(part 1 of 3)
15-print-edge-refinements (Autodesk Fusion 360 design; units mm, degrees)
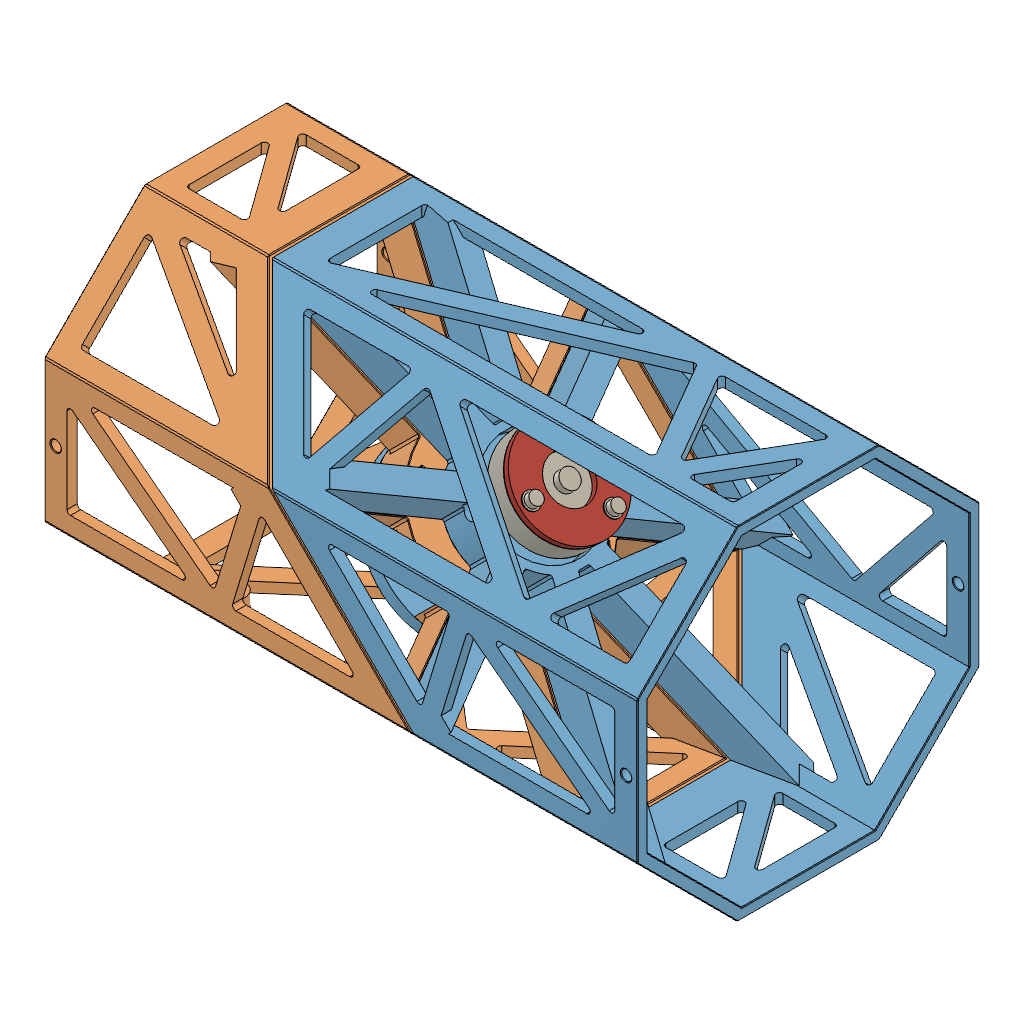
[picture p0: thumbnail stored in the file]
part number: 2026-11-02-20-17-55-344
part number: 2026-11-02-20-17-59-218
part number: 2026-11-02-20-17-59-224
part number: 2026-11-02-20-19-00-695
part number: 2026-11-02-20-19-03-009
part number: 2026-11-02-20-19-04-949
part number: 2026-11-02-20-19-06-912
part number: 2026-11-02-20-19-11-903
part number: 2026-11-02-20-19-12-666
part number: 2026-11-02-20-19-12-978
part number: 2026-11-02-20-19-13-740
part number: 2026-11-02-20-19-14-532
part number: 2026-11-02-20-19-15-361
part number: 2026-11-02-20-19-17-468
part number: 2026-11-02-20-19-19-583
part number: 2026-11-02-20-19-25-638
part number: 2026-11-02-20-19-39-091
parameter "bodyWidth" = 150 comment "Regular octagon across flats; corner diameter is larger."
parameter "bodyLength" = 260 comment "Overall straight length of the shared master blank."
parameter "splitAngle" = 45 comment "Keep this lesson angle at45 degrees."
parameter "faceGap" = 1 comment "Gap between the two printed joint faces."
parameter "wall" = 4.5 comment "Integrated shell and side brace radial thickness."
parameter "faceHalfWidth" = 31.066 (= "bodyWidth * ( sqrt(2) - 1 ) / 2") comment "Half-width of each outer planar facet."
parameter "memberWidth" = 8 comment "Nominal brace and corner chord width in a facet."
parameter "nodeHalfWidth" = 27.066 (= "faceHalfWidth - memberWidth / 2") comment "Chord centerlines measured from facet center."
parameter "jointNodeQ" = 7 comment "First truss skeleton row from the center joint plane."
parameter "endRim" = 10 comment "Uncut axial rim at each distant end."
parameter "endNodeX" = 124 (= "bodyLength / 2 - endRim + memberWidth / 2") comment "Last skeleton row before aperture inset."
parameter "apertureRadius" = 1.5 comment "Rounded internal corners at triangular openings."
parameter "spokeWidth" = 10 comment "Width of each deep bearing bulkhead spoke."
parameter "spokeDepth" = 18 comment "Bulkhead depth normal to the diagonal joint face."
parameter "carrierOD" = 52 comment "Outside of integrated A front bearing carrier."
parameter "rearCarrierClearance" = 46 comment "Internal carrier relief above front bearing shoulder."
parameter "tubeCornerChamfer" = 0.5 comment "Exposed outside octagon corner bevel."
parameter "tubeRimChamfer" = 0.3 comment "End rim and print-contact edge relief."
parameter "cordStation" = 125 (= "bodyLength / 2 - endRim / 2") comment "Load-test cord port center measured along body X."
parameter "bearingOD" = 22 comment "608 measured outside diameter."
parameter "bearingID" = 8 comment "608 bore."
parameter "bearingWidth" = 7 comment "608 width."
parameter "seatAllowance" = 0.2 comment "Trial DIAMETRAL clearance; choose with printed coupon."
parameter "seatDiameter" = 22.2 (= "bearingOD + seatAllowance") comment "Measured fit controls this."
parameter "coreOD" = 44 comment "Bearing holder outer diameter."
parameter "raceRelief" = 19.5 comment "Outer-ring shoulder opening; verify seals."
parameter "frontSeatDepth" = 7.1 comment "0.1 mm outer-ring axial allowance."
parameter "rearSeatDepth" = 7.2 comment "0.2 mm outer-ring axial float."
parameter "shoulder" = 3 comment "Backing behind each bearing seat."
parameter "supportSpacer" = 12 comment "Purchased metal M3 spacer length."
parameter "supportCircle" = 34 comment "Three M3 support bolts."
parameter "supportSpacerOD" = 6 comment "Purchased spacer outside diameter."
parameter "capThickness" = 3 comment "Both printed outer-ring retaining caps."
parameter "m3Clearance" = 3.3 comment "M3 through holes."
parameter "m4Clearance" = 4.3 comment "M4 through holes."
parameter "qFront" = 0.5 (= "faceGap / 2") comment "Front bearing starts at A mating face."
parameter "qFrontBack" = 10.6 (= "qFront + frontSeatDepth + shoulder") comment "End of integrated A holder."
parameter "qRearBase" = 22.6 (= "qFrontBack + supportSpacer") comment "Start of removable rear holder."
parameter "qRearBearing" = 25.6 (= "qRearBase + shoulder") comment "Rear bearing inner end."
parameter "qRearEnd" = 32.8 (= "qRearBearing + rearSeatDepth") comment "Rear holder outer end."
parameter "bearingSpacing" = 25.1 (= "qRearBearing - qFront") comment "Derived support-center spacing, not a bearing rating."
parameter "mountOD" = 76 comment "B mount and F flange outside diameter."
parameter "mountCircle" = 64 comment "Four M4 attachment holes."
parameter "mountOpening" = 50.3 comment "B through opening."
parameter "hubFace" = -23 comment "Metal hub flat mounting face."
parameter "adapterThickness" = 6 comment "F flange and metal compression sleeve length."
parameter "pilotDiameter" = 50 comment "F shallow centering pilot."
parameter "pilotInside" = 34 comment "Clearance around metal hub."
parameter "pilotHeight" = 2 comment "Short pilot only."
parameter "hubHoleSpacing" = 16 comment "Metal Sonic hub square hole spacing."
parameter "sleeveOD" = 8 comment "M4 metal compression sleeves."
parameter "sleeveAllowance" = 0.2 comment "Trial DIAMETRAL sleeve clearance."
parameter "shaftClearance" = 8.5 comment "F clearance hole; not a bearing."
parameter "nutAF" = 7.2 comment "M4 nominal 7 AF nut trial pocket."
parameter "nutDepth" = 4 comment "Open front M4 nut pocket."
parameter "rootRadius" = 1 comment "Hub-to-wall blend."
parameter "entryChamfer" = 0.4 comment "Assembly lead-in."
parameter "bedRelief" = 0.3 comment "Bed-contact edge allowance."
parameter "driverPort" = 5 comment "Clearance for bare3 mm hex-key shafts; bulky bit holders do not fit."
parameter "accessPadWidth" = 12 comment "Reinforced access-port capsule width."
parameter "accessPadExtra" = 2 comment "Local inward reinforcement beyond nominal side wall."
parameter "printEntryRelief" = 0.3 comment "Small nut, sleeve and free shaft-hole bed-mouth lead-in; not a bore size."
sketch "01 Master Octagon" plane through (0, 0, 0) normal (1, 0, 0) x axis (0, 0, -1)
  line L1 (31.066, 75) -> (75, 31.066)
  line L2 (-31.066, 75) -> (31.066, 75)
  line L3 (-75, 31.066) -> (-31.066, 75)
  line L4 (-75, -31.066) -> (-75, 31.066)
  line L5 (-31.066, -75) -> (-75, -31.066)
  line L6 (31.066, -75) -> (-31.066, -75)
  line L7 (75, -31.066) -> (31.066, -75)
  line L8 (75, 31.066) -> (75, -31.066)
  point P1 (0, 0)
  point P10 (0, 0)
  point P3 (31.066, 75)
  point P8 (31.066, -75)
  coincident P1 P10
  horizontal L2
  dimension "d59" distance P3 P8 = 150 (= "bodyWidth")
extrude "Extrude1" new body sketch "01 Master Octagon" distance 260 (= "bodyLength")
work_plane "WorkPlane1" RotateAngle 45 (= "splitAngle") ExtraOffset 0
split "Split1"
offset_faces "OffsetFaces1" distance -0.5 (= "-faceGap / 2")
offset_faces "OffsetFaces2" distance -0.5 (= "-faceGap / 2")
component_from_bodies "Body->Comp1"
component_from_bodies "Body->Comp2"
shell "Shell1" innerThickness 4.5 (= "wall")
shell "Shell1" innerThickness 4.5 (= "wall")
work_plane "WorkPlane1" RotateAngle -90 ExtraOffset 0
work_plane "WorkPlane2" AlongDistance 75 (= "bodyWidth / 2") ExtraOffset 0
sketch "A Facet 0 Triangle 1" plane through (0, 75, 0) normal (0, 1, 0) x axis (1, 0, 0)
  line L1 (-65.1005, -27.066) -> (-65.1005, 27.066)
  line L2 (60.9665, 27.066) -> (-65.1005, -27.066)
  line L3 (-65.1005, 27.066) -> (60.9665, 27.066)
  line L4 (-61.1005, -20.9953) -> (-61.1005, 23.066)
  line L5 (41.513, 23.066) -> (-61.1005, -20.9953)
  line L6 (-61.1005, 23.066) -> (41.513, 23.066)
  point P1 (0, 0)
  point P2 (-65.1005, 27.066)
  point P3 (-65.1005, -27.066)
  point P4 (60.9665, 27.066)
  dimension "d72" distance P1 P2 = 65.1005 (= "Linear Dimension-2")
  dimension "d73" distance P1 P2 = 27.066 (= "Linear Dimension-3")
  dimension "d74" distance P1 P3 = 65.1005 (= "Linear Dimension-4")
  dimension "d75" distance P1 P3 = 27.066 (= "Linear Dimension-5")
  dimension "d76" distance P1 P4 = 60.9665 (= "Linear Dimension-6")
  dimension "d77" distance P1 P4 = 27.066 (= "Linear Dimension-7")
  dimension "d78" = -4 (= "-memberWidth / 2")
extrude "Extrude1" cut sketch "A Facet 0 Triangle 1" profile of L5 L6 L4 against normal blind 4.7 (magnitude of "-( wall + 0.2 mm )")
sketch "A Facet 0 Triangle 2" plane through (0, 75, 0) normal (0, 1, 0) x axis (1, 0, 0)
  line L1 (60.9665, 27.066) -> (-65.1005, -27.066)
  line L2 (92.4832, -27.066) -> (60.9665, 27.066)
  line L3 (-65.1005, -27.066) -> (92.4832, -27.066)
  line L4 (59.2912, 21.9935) -> (-45.647, -23.066)
  line L5 (85.5258, -23.066) -> (59.2912, 21.9935)
  line L6 (-45.647, -23.066) -> (85.5258, -23.066)
  point P1 (0, 0)
  point P2 (-65.1005, -27.066)
  point P3 (60.9665, 27.066)
  point P4 (92.4832, -27.066)
  dimension "d81" distance P1 P2 = 65.1005 (= "Linear Dimension-2")
  dimension "d82" distance P1 P2 = 27.066 (= "Linear Dimension-3")
  dimension "d83" distance P1 P3 = 60.9665 (= "Linear Dimension-4")
  dimension "d84" distance P1 P3 = 27.066 (= "Linear Dimension-5")
  dimension "d85" distance P1 P4 = 92.4832 (= "Linear Dimension-6")
  dimension "d86" distance P1 P4 = 27.066 (= "Linear Dimension-7")
  dimension "d87" = 4 (= "memberWidth / 2")
extrude "Extrude2" cut sketch "A Facet 0 Triangle 2" profile of L5 L6 L4 against normal blind 4.7 (magnitude of "-( wall + 0.2 mm )")
sketch "A Facet 0 Triangle 3" plane through (0, 75, 0) normal (0, 1, 0) x axis (1, 0, 0)
  line L1 (92.4832, -27.066) -> (60.9665, 27.066)
  line L2 (124, 27.066) -> (92.4832, -27.066)
  line L3 (60.9665, 27.066) -> (124, 27.066)
  line L4 (92.4832, -19.1161) -> (67.924, 23.066)
  line L5 (117.0425, 23.066) -> (92.4832, -19.1161)
  line L6 (67.924, 23.066) -> (117.0425, 23.066)
  point P1 (0, 0)
  point P2 (60.9665, 27.066)
  point P3 (92.4832, -27.066)
  point P4 (124, 27.066)
  dimension "d90" distance P1 P2 = 60.9665 (= "Linear Dimension-2")
  dimension "d91" distance P1 P2 = 27.066 (= "Linear Dimension-3")
  dimension "d92" distance P1 P3 = 92.4832 (= "Linear Dimension-4")
  dimension "d93" distance P1 P3 = 27.066 (= "Linear Dimension-5")
  dimension "d94" distance P1 P4 = 124 (= "Linear Dimension-6")
  dimension "d95" distance P1 P4 = 27.066 (= "Linear Dimension-7")
  dimension "d96" = -4 (= "-memberWidth / 2")
extrude "Extrude3" cut sketch "A Facet 0 Triangle 3" profile of L5 L6 L4 against normal blind 4.7 (magnitude of "-( wall + 0.2 mm )")
sketch "A Facet 0 Triangle 4" plane through (0, 75, 0) normal (0, 1, 0) x axis (1, 0, 0)
  line L1 (124, 27.066) -> (92.4832, -27.066)
  line L2 (124, -27.066) -> (124, 27.066)
  line L3 (92.4832, -27.066) -> (124, -27.066)
  line L4 (120, 12.2459) -> (99.4407, -23.066)
  line L5 (120, -23.066) -> (120, 12.2459)
  line L6 (99.4407, -23.066) -> (120, -23.066)
  point P1 (0, 0)
  point P2 (92.4832, -27.066)
  point P3 (124, 27.066)
  point P4 (124, -27.066)
  dimension "d99" distance P1 P2 = 92.4832 (= "Linear Dimension-2")
  dimension "d100" distance P1 P2 = 27.066 (= "Linear Dimension-3")
  dimension "d101" distance P1 P3 = 124 (= "Linear Dimension-4")
  dimension "d102" distance P1 P3 = 27.066 (= "Linear Dimension-5")
  dimension "d103" distance P1 P4 = 124 (= "Linear Dimension-6")
  dimension "d104" distance P1 P4 = 27.066 (= "Linear Dimension-7")
  dimension "d105" = 4 (= "memberWidth / 2")
extrude "Extrude4" cut sketch "A Facet 0 Triangle 4" profile of L5 L6 L4 against normal blind 4.7 (magnitude of "-( wall + 0.2 mm )")
fillet "Fillet1" radius 1.5 (= "apertureRadius")
work_plane "WorkPlane3" RotateAngle -45 ExtraOffset 0
work_plane "WorkPlane4" AlongDistance 75 (= "bodyWidth / 2") ExtraOffset 0
sketch "A Facet 45 Triangle 1" plane through (0, 53.033, 53.033) normal (0, 0.7071, 0.7071) x axis (1, 0, 0)
  line L1 (-23.9949, -27.066) -> (-62.2721, 27.066)
  line L2 (-0.1814, 27.066) -> (-23.9949, -27.066)
  line L3 (-62.2721, 27.066) -> (-0.1814, 27.066)
  line L4 (-24.81, -18.9852) -> (-54.5447, 23.066)
  line L5 (-6.311, 23.066) -> (-24.81, -18.9852)
  line L6 (-54.5447, 23.066) -> (-6.311, 23.066)
  point P1 (0, 0)
  point P2 (-62.2721, 27.066)
  point P3 (-23.9949, -27.066)
  point P4 (-0.1814, 27.066)
  dimension "d114" distance P1 P2 = 62.2721 (= "Linear Dimension-2")
  dimension "d115" distance P1 P2 = 27.066 (= "Linear Dimension-3")
  dimension "d116" distance P1 P3 = 23.9949 (= "Linear Dimension-4")
  dimension "d117" distance P1 P3 = 27.066 (= "Linear Dimension-5")
  dimension "d118" distance P1 P4 = 0.1814 (= "Linear Dimension-6")
  dimension "d119" distance P1 P4 = 27.066 (= "Linear Dimension-7")
  dimension "d120" = -4 (= "-memberWidth / 2")
extrude "Extrude5" cut sketch "A Facet 45 Triangle 1" profile of L5 L6 L4 against normal blind 4.7 (magnitude of "-( wall + 0.2 mm )")
sketch "A Facet 45 Triangle 2" plane through (0, 53.033, 53.033) normal (0, 0.7071, 0.7071) x axis (1, 0, 0)
  line L1 (-0.1814, 27.066) -> (-23.9949, -27.066)
  line L2 (74.6684, -27.066) -> (-0.1814, 27.066)
  line L3 (-23.9949, -27.066) -> (74.6684, -27.066)
  line L4 (1.4863, 20.9235) -> (-17.8653, -23.066)
  line L5 (62.3117, -23.066) -> (1.4863, 20.9235)
  line L6 (-17.8653, -23.066) -> (62.3117, -23.066)
  point P1 (0, 0)
  point P2 (-23.9949, -27.066)
  point P3 (-0.1814, 27.066)
  point P4 (74.6684, -27.066)
  dimension "d123" distance P1 P2 = 23.9949 (= "Linear Dimension-2")
  dimension "d124" distance P1 P2 = 27.066 (= "Linear Dimension-3")
  dimension "d125" distance P1 P3 = 0.1814 (= "Linear Dimension-4")
  dimension "d126" distance P1 P3 = 27.066 (= "Linear Dimension-5")
  dimension "d127" distance P1 P4 = 74.6684 (= "Linear Dimension-6")
  dimension "d128" distance P1 P4 = 27.066 (= "Linear Dimension-7")
  dimension "d129" = 4 (= "memberWidth / 2")
extrude "Extrude6" cut sketch "A Facet 45 Triangle 2" profile of L5 L6 L4 against normal blind 4.7 (magnitude of "-( wall + 0.2 mm )")
sketch "A Facet 45 Triangle 3" plane through (0, 53.033, 53.033) normal (0, 0.7071, 0.7071) x axis (1, 0, 0)
  line L1 (74.6684, -27.066) -> (-0.1814, 27.066)
  line L2 (124, 27.066) -> (74.6684, -27.066)
  line L3 (-0.1814, 27.066) -> (124, 27.066)
  line L4 (74.1179, -21.7315) -> (12.1753, 23.066)
  line L5 (114.9429, 23.066) -> (74.1179, -21.7315)
  line L6 (12.1753, 23.066) -> (114.9429, 23.066)
  point P1 (0, 0)
  point P2 (-0.1814, 27.066)
  point P3 (74.6684, -27.066)
  point P4 (124, 27.066)
  dimension "d132" distance P1 P2 = 0.1814 (= "Linear Dimension-2")
  dimension "d133" distance P1 P2 = 27.066 (= "Linear Dimension-3")
  dimension "d134" distance P1 P3 = 74.6684 (= "Linear Dimension-4")
  dimension "d135" distance P1 P3 = 27.066 (= "Linear Dimension-5")
  dimension "d136" distance P1 P4 = 124 (= "Linear Dimension-6")
  dimension "d137" distance P1 P4 = 27.066 (= "Linear Dimension-7")
  dimension "d138" = -4 (= "-memberWidth / 2")
extrude "Extrude7" cut sketch "A Facet 45 Triangle 3" profile of L5 L6 L4 against normal blind 4.7 (magnitude of "-( wall + 0.2 mm )")
sketch "A Facet 45 Triangle 4" plane through (0, 53.033, 53.033) normal (0, 0.7071, 0.7071) x axis (1, 0, 0)
  line L1 (124, 27.066) -> (74.6684, -27.066)
  line L2 (124, -27.066) -> (124, 27.066)
  line L3 (74.6684, -27.066) -> (124, -27.066)
  line L4 (120, 16.7383) -> (83.7255, -23.066)
  line L5 (120, -23.066) -> (120, 16.7383)
  line L6 (83.7255, -23.066) -> (120, -23.066)
  point P1 (0, 0)
  point P2 (74.6684, -27.066)
  point P3 (124, 27.066)
  point P4 (124, -27.066)
  dimension "d141" distance P1 P2 = 74.6684 (= "Linear Dimension-2")
  dimension "d142" distance P1 P2 = 27.066 (= "Linear Dimension-3")
  dimension "d143" distance P1 P3 = 124 (= "Linear Dimension-4")
  dimension "d144" distance P1 P3 = 27.066 (= "Linear Dimension-5")
  dimension "d145" distance P1 P4 = 124 (= "Linear Dimension-6")
  dimension "d146" distance P1 P4 = 27.066 (= "Linear Dimension-7")
  dimension "d147" = 4 (= "memberWidth / 2")
extrude "Extrude8" cut sketch "A Facet 45 Triangle 4" profile of L5 L6 L4 against normal blind 4.7 (magnitude of "-( wall + 0.2 mm )")
fillet "Fillet2" radius 1.5 (= "apertureRadius")
work_plane "WorkPlane5" RotateAngle 0 ExtraOffset 0
work_plane "WorkPlane6" AlongDistance 75 (= "bodyWidth / 2") ExtraOffset 0
sketch "A Facet 90 Triangle 1" plane through (0, 0, 75) normal (0, 0, 1) x axis (1, 0, 0)
  line L1 (36.9655, -27.066) -> (-17.1665, 27.066)
  line L2 (53.4167, 27.066) -> (36.9655, -27.066)
  line L3 (-17.1665, 27.066) -> (53.4167, 27.066)
  line L4 (35.0777, -19.5214) -> (-7.5097, 23.066)
  line L5 (48.0205, 23.066) -> (35.0777, -19.5214)
  line L6 (-7.5097, 23.066) -> (48.0205, 23.066)
  point P1 (0, 0)
  point P2 (-17.1665, 27.066)
  point P3 (36.9655, -27.066)
  point P4 (53.4167, 27.066)
  dimension "d156" distance P1 P2 = 17.1665 (= "Linear Dimension-2")
  dimension "d157" distance P1 P2 = 27.066 (= "Linear Dimension-3")
  dimension "d158" distance P1 P3 = 36.9655 (= "Linear Dimension-4")
  dimension "d159" distance P1 P3 = 27.066 (= "Linear Dimension-5")
  dimension "d160" distance P1 P4 = 53.4167 (= "Linear Dimension-6")
  dimension "d161" distance P1 P4 = 27.066 (= "Linear Dimension-7")
  dimension "d162" = -4 (= "-memberWidth / 2")
extrude "Extrude9" cut sketch "A Facet 90 Triangle 1" profile of L5 L6 L4 against normal blind 4.7 (magnitude of "-( wall + 0.2 mm )")
sketch "A Facet 90 Triangle 2" plane through (0, 0, 75) normal (0, 0, 1) x axis (1, 0, 0)
  line L1 (53.4167, 27.066) -> (36.9655, -27.066)
  line L2 (124, -27.066) -> (53.4167, 27.066)
  line L3 (36.9655, -27.066) -> (124, -27.066)
  line L4 (55.5648, 20.3777) -> (42.3618, -23.066)
  line L5 (112.2115, -23.066) -> (55.5648, 20.3777)
  line L6 (42.3618, -23.066) -> (112.2115, -23.066)
  point P1 (0, 0)
  point P2 (36.9655, -27.066)
  point P3 (53.4167, 27.066)
  point P4 (124, -27.066)
  dimension "d165" distance P1 P2 = 36.9655 (= "Linear Dimension-2")
  dimension "d166" distance P1 P2 = 27.066 (= "Linear Dimension-3")
  dimension "d167" distance P1 P3 = 53.4167 (= "Linear Dimension-4")
  dimension "d168" distance P1 P3 = 27.066 (= "Linear Dimension-5")
  dimension "d169" distance P1 P4 = 124 (= "Linear Dimension-6")
  dimension "d170" distance P1 P4 = 27.066 (= "Linear Dimension-7")
  dimension "d171" = 4 (= "memberWidth / 2")
extrude "Extrude10" cut sketch "A Facet 90 Triangle 2" profile of L5 L6 L4 against normal blind 4.7 (magnitude of "-( wall + 0.2 mm )")
sketch "A Facet 90 Triangle 3" plane through (0, 0, 75) normal (0, 0, 1) x axis (1, 0, 0)
  line L1 (124, -27.066) -> (53.4167, 27.066)
  line L2 (124, 27.066) -> (124, -27.066)
  line L3 (53.4167, 27.066) -> (124, 27.066)
  line L4 (120, -18.9574) -> (65.2053, 23.066)
  line L5 (120, 23.066) -> (120, -18.9574)
  line L6 (65.2053, 23.066) -> (120, 23.066)
  point P1 (0, 0)
  point P2 (53.4167, 27.066)
  point P3 (124, -27.066)
  point P4 (124, 27.066)
  dimension "d174" distance P1 P2 = 53.4167 (= "Linear Dimension-2")
  dimension "d175" distance P1 P2 = 27.066 (= "Linear Dimension-3")
  dimension "d176" distance P1 P3 = 124 (= "Linear Dimension-4")
  dimension "d177" distance P1 P3 = 27.066 (= "Linear Dimension-5")
  dimension "d178" distance P1 P4 = 124 (= "Linear Dimension-6")
  dimension "d179" distance P1 P4 = 27.066 (= "Linear Dimension-7")
  dimension "d180" = -4 (= "-memberWidth / 2")
extrude "Extrude11" cut sketch "A Facet 90 Triangle 3" profile of L5 L6 L4 against normal blind 4.7 (magnitude of "-( wall + 0.2 mm )")
fillet "Fillet3" radius 1.5 (= "apertureRadius")
work_plane "WorkPlane7" RotateAngle 45 ExtraOffset 0
work_plane "WorkPlane8" AlongDistance 75 (= "bodyWidth / 2") ExtraOffset 0
sketch "A Facet 135 Triangle 1" plane through (0, -53.033, 53.033) normal (0, -0.7071, 0.7071) x axis (1, 0, 0)
  line L1 (82.0711, -27.066) -> (43.7939, 27.066)
  line L2 (124, 27.066) -> (82.0711, -27.066)
  line L3 (43.7939, 27.066) -> (124, 27.066)
  line L4 (82.2175, -20.3449) -> (51.5213, 23.066)
  line L5 (115.8422, 23.066) -> (82.2175, -20.3449)
  line L6 (51.5213, 23.066) -> (115.8422, 23.066)
  point P1 (0, 0)
  point P2 (43.7939, 27.066)
  point P3 (82.0711, -27.066)
  point P4 (124, 27.066)
  dimension "d189" distance P1 P2 = 43.7939 (= "Linear Dimension-2")
  dimension "d190" distance P1 P2 = 27.066 (= "Linear Dimension-3")
  dimension "d191" distance P1 P3 = 82.0711 (= "Linear Dimension-4")
  dimension "d192" distance P1 P3 = 27.066 (= "Linear Dimension-5")
  dimension "d193" distance P1 P4 = 124 (= "Linear Dimension-6")
  dimension "d194" distance P1 P4 = 27.066 (= "Linear Dimension-7")
  dimension "d195" = -4 (= "-memberWidth / 2")
extrude "Extrude12" cut sketch "A Facet 135 Triangle 1" profile of L5 L6 L4 against normal blind 4.7 (magnitude of "-( wall + 0.2 mm )")
sketch "A Facet 135 Triangle 2" plane through (0, -53.033, 53.033) normal (0, -0.7071, 0.7071) x axis (1, 0, 0)
  line L1 (124, 27.066) -> (82.0711, -27.066)
  line L2 (124, -27.066) -> (124, 27.066)
  line L3 (82.0711, -27.066) -> (124, -27.066)
  line L4 (120, 15.3697) -> (90.2289, -23.066)
  line L5 (120, -23.066) -> (120, 15.3697)
  line L6 (90.2289, -23.066) -> (120, -23.066)
  point P1 (0, 0)
  point P2 (82.0711, -27.066)
  point P3 (124, 27.066)
  point P4 (124, -27.066)
  dimension "d198" distance P1 P2 = 82.0711 (= "Linear Dimension-2")
  dimension "d199" distance P1 P2 = 27.066 (= "Linear Dimension-3")
  dimension "d200" distance P1 P3 = 124 (= "Linear Dimension-4")
  dimension "d201" distance P1 P3 = 27.066 (= "Linear Dimension-5")
  dimension "d202" distance P1 P4 = 124 (= "Linear Dimension-6")
  dimension "d203" distance P1 P4 = 27.066 (= "Linear Dimension-7")
  dimension "d204" = 4 (= "memberWidth / 2")
extrude "Extrude13" cut sketch "A Facet 135 Triangle 2" profile of L5 L6 L4 against normal blind 4.7 (magnitude of "-( wall + 0.2 mm )")
fillet "Fillet4" radius 1.5 (= "apertureRadius")
work_plane "WorkPlane9" RotateAngle 90 ExtraOffset 0
work_plane "WorkPlane10" AlongDistance 75 (= "bodyWidth / 2") ExtraOffset 0
sketch "A Facet 180 Triangle 1" plane through (0, -75, 0) normal (0, -1, 0) x axis (-1, 0, 0)
  line L1 (-84.8995, 27.066) -> (-84.8995, -27.066)
  line L2 (-124, -27.066) -> (-84.8995, 27.066)
  line L3 (-84.8995, -27.066) -> (-124, -27.066)
  line L4 (-88.8995, 14.697) -> (-88.8995, -23.066)
  line L5 (-116.1764, -23.066) -> (-88.8995, 14.697)
  line L6 (-88.8995, -23.066) -> (-116.1764, -23.066)
  point P1 (0, 0)
  point P2 (-84.8995, -27.066)
  point P3 (-84.8995, 27.066)
  point P4 (-124, -27.066)
  dimension "d213" distance P1 P2 = 84.8995 (= "Linear Dimension-2")
  dimension "d214" distance P1 P2 = 27.066 (= "Linear Dimension-3")
  dimension "d215" distance P1 P3 = 84.8995 (= "Linear Dimension-4")
  dimension "d216" distance P1 P3 = 27.066 (= "Linear Dimension-5")
  dimension "d217" distance P1 P4 = 124 (= "Linear Dimension-6")
  dimension "d218" distance P1 P4 = 27.066 (= "Linear Dimension-7")
  dimension "d219" = -4 (= "-memberWidth / 2")
extrude "Extrude14" cut sketch "A Facet 180 Triangle 1" profile of L5 L6 L4 against normal blind 4.7 (magnitude of "-( wall + 0.2 mm )")
sketch "A Facet 180 Triangle 2" plane through (0, -75, 0) normal (0, -1, 0) x axis (-1, 0, 0)
  line L1 (-124, -27.066) -> (-84.8995, 27.066)
  line L2 (-124, 27.066) -> (-124, -27.066)
  line L3 (-84.8995, 27.066) -> (-124, 27.066)
  line L4 (-120, -14.697) -> (-92.7231, 23.066)
  line L5 (-120, 23.066) -> (-120, -14.697)
  line L6 (-92.7231, 23.066) -> (-120, 23.066)
  point P1 (0, 0)
  point P2 (-84.8995, 27.066)
  point P3 (-124, -27.066)
  point P4 (-124, 27.066)
  dimension "d222" distance P1 P2 = 84.8995 (= "Linear Dimension-2")
  dimension "d223" distance P1 P2 = 27.066 (= "Linear Dimension-3")
  dimension "d224" distance P1 P3 = 124 (= "Linear Dimension-4")
  dimension "d225" distance P1 P3 = 27.066 (= "Linear Dimension-5")
  dimension "d226" distance P1 P4 = 124 (= "Linear Dimension-6")
  dimension "d227" distance P1 P4 = 27.066 (= "Linear Dimension-7")
  dimension "d228" = 4 (= "memberWidth / 2")
extrude "Extrude15" cut sketch "A Facet 180 Triangle 2" profile of L5 L6 L4 against normal blind 4.7 (magnitude of "-( wall + 0.2 mm )")
fillet "Fillet5" radius 1.5 (= "apertureRadius")
work_plane "WorkPlane11" RotateAngle 135 ExtraOffset 0
work_plane "WorkPlane12" AlongDistance 75 (= "bodyWidth / 2") ExtraOffset 0
sketch "A Facet 225 Triangle 1" plane through (0, -53.033, -53.033) normal (0, -0.7071, -0.7071) x axis (1, 0, 0)
  line L1 (43.7939, -27.066) -> (82.0711, 27.066)
  line L2 (124, 27.066) -> (43.7939, -27.066)
  line L3 (82.0711, 27.066) -> (124, 27.066)
  line L4 (59.6927, -11.51) -> (84.1416, 23.066)
  line L5 (110.9231, 23.066) -> (59.6927, -11.51)
  line L6 (84.1416, 23.066) -> (110.9231, 23.066)
  point P1 (0, 0)
  point P2 (82.0711, 27.066)
  point P3 (43.7939, -27.066)
  point P4 (124, 27.066)
  dimension "d237" distance P1 P2 = 82.0711 (= "Linear Dimension-2")
  dimension "d238" distance P1 P2 = 27.066 (= "Linear Dimension-3")
  dimension "d239" distance P1 P3 = 43.7939 (= "Linear Dimension-4")
  dimension "d240" distance P1 P3 = 27.066 (= "Linear Dimension-5")
  dimension "d241" distance P1 P4 = 124 (= "Linear Dimension-6")
  dimension "d242" distance P1 P4 = 27.066 (= "Linear Dimension-7")
  dimension "d243" = -4 (= "-memberWidth / 2")
extrude "Extrude16" cut sketch "A Facet 225 Triangle 1" profile of L5 L6 L4 against normal blind 4.7 (magnitude of "-( wall + 0.2 mm )")
sketch "A Facet 225 Triangle 2" plane through (0, -53.033, -53.033) normal (0, -0.7071, -0.7071) x axis (1, 0, 0)
  line L1 (124, 27.066) -> (43.7939, -27.066)
  line L2 (124, -27.066) -> (124, 27.066)
  line L3 (43.7939, -27.066) -> (124, -27.066)
  line L4 (120, 19.5406) -> (56.8709, -23.066)
  line L5 (120, -23.066) -> (120, 19.5406)
  line L6 (56.8709, -23.066) -> (120, -23.066)
  point P1 (0, 0)
  point P2 (43.7939, -27.066)
  point P3 (124, 27.066)
  point P4 (124, -27.066)
  dimension "d246" distance P1 P2 = 43.7939 (= "Linear Dimension-2")
  dimension "d247" distance P1 P2 = 27.066 (= "Linear Dimension-3")
  dimension "d248" distance P1 P3 = 124 (= "Linear Dimension-4")
  dimension "d249" distance P1 P3 = 27.066 (= "Linear Dimension-5")
  dimension "d250" distance P1 P4 = 124 (= "Linear Dimension-6")
  dimension "d251" distance P1 P4 = 27.066 (= "Linear Dimension-7")
  dimension "d252" = 4 (= "memberWidth / 2")
extrude "Extrude17" cut sketch "A Facet 225 Triangle 2" profile of L5 L6 L4 against normal blind 4.7 (magnitude of "-( wall + 0.2 mm )")
fillet "Fillet6" radius 1.5 (= "apertureRadius")
work_plane "WorkPlane13" RotateAngle 180 ExtraOffset 0
work_plane "WorkPlane14" AlongDistance 75 (= "bodyWidth / 2") ExtraOffset 0
sketch "A Facet 270 Triangle 1" plane through (0, 0, -75) normal (0, 0, -1) x axis (-1, 0, 0)
  line L1 (17.1665, 27.066) -> (-36.9655, -27.066)
  line L2 (-80.4828, -27.066) -> (17.1665, 27.066)
  line L3 (-36.9655, -27.066) -> (-80.4828, -27.066)
  line L4 (-5.7896, 9.7668) -> (-38.6224, -23.066)
  line L5 (-65.0169, -23.066) -> (-5.7896, 9.7668)
  line L6 (-38.6224, -23.066) -> (-65.0169, -23.066)
  point P1 (0, 0)
  point P2 (-36.9655, -27.066)
  point P3 (17.1665, 27.066)
  point P4 (-80.4828, -27.066)
  dimension "d261" distance P1 P2 = 36.9655 (= "Linear Dimension-2")
  dimension "d262" distance P1 P2 = 27.066 (= "Linear Dimension-3")
  dimension "d263" distance P1 P3 = 17.1665 (= "Linear Dimension-4")
  dimension "d264" distance P1 P3 = 27.066 (= "Linear Dimension-5")
  dimension "d265" distance P1 P4 = 80.4828 (= "Linear Dimension-6")
  dimension "d266" distance P1 P4 = 27.066 (= "Linear Dimension-7")
  dimension "d267" = -4 (= "-memberWidth / 2")
extrude "Extrude18" cut sketch "A Facet 270 Triangle 1" profile of L5 L6 L4 against normal blind 4.7 (magnitude of "-( wall + 0.2 mm )")
sketch "A Facet 270 Triangle 2" plane through (0, 0, -75) normal (0, 0, -1) x axis (-1, 0, 0)
  line L1 (-80.4828, -27.066) -> (17.1665, 27.066)
  line L2 (-124, 27.066) -> (-80.4828, -27.066)
  line L3 (17.1665, 27.066) -> (-124, 27.066)
  line L4 (-79.4759, -21.9343) -> (1.7007, 23.066)
  line L5 (-115.6521, 23.066) -> (-79.4759, -21.9343)
  line L6 (1.7007, 23.066) -> (-115.6521, 23.066)
  point P1 (0, 0)
  point P2 (17.1665, 27.066)
  point P3 (-80.4828, -27.066)
  point P4 (-124, 27.066)
  dimension "d270" distance P1 P2 = 17.1665 (= "Linear Dimension-2")
  dimension "d271" distance P1 P2 = 27.066 (= "Linear Dimension-3")
  dimension "d272" distance P1 P3 = 80.4828 (= "Linear Dimension-4")
  dimension "d273" distance P1 P3 = 27.066 (= "Linear Dimension-5")
  dimension "d274" distance P1 P4 = 124 (= "Linear Dimension-6")
  dimension "d275" distance P1 P4 = 27.066 (= "Linear Dimension-7")
  dimension "d276" = 4 (= "memberWidth / 2")
extrude "Extrude19" cut sketch "A Facet 270 Triangle 2" profile of L5 L6 L4 against normal blind 4.7 (magnitude of "-( wall + 0.2 mm )")
sketch "A Facet 270 Triangle 3" plane through (0, 0, -75) normal (0, 0, -1) x axis (-1, 0, 0)
  line L1 (-124, 27.066) -> (-80.4828, -27.066)
  line L2 (-124, -27.066) -> (-124, 27.066)
  line L3 (-80.4828, -27.066) -> (-124, -27.066)
  line L4 (-120, 15.7062) -> (-88.8307, -23.066)
  line L5 (-120, -23.066) -> (-120, 15.7062)
  line L6 (-88.8307, -23.066) -> (-120, -23.066)
  point P1 (0, 0)
  point P2 (-80.4828, -27.066)
  point P3 (-124, 27.066)
  point P4 (-124, -27.066)
  dimension "d279" distance P1 P2 = 80.4828 (= "Linear Dimension-2")
  dimension "d280" distance P1 P2 = 27.066 (= "Linear Dimension-3")
  dimension "d281" distance P1 P3 = 124 (= "Linear Dimension-4")
  dimension "d282" distance P1 P3 = 27.066 (= "Linear Dimension-5")
  dimension "d283" distance P1 P4 = 124 (= "Linear Dimension-6")
  dimension "d284" distance P1 P4 = 27.066 (= "Linear Dimension-7")
  dimension "d285" = -4 (= "-memberWidth / 2")
extrude "Extrude20" cut sketch "A Facet 270 Triangle 3" profile of L5 L6 L4 against normal blind 4.7 (magnitude of "-( wall + 0.2 mm )")
fillet "Fillet7" radius 1.5 (= "apertureRadius")
work_plane "WorkPlane15" RotateAngle 225 ExtraOffset 0
work_plane "WorkPlane16" AlongDistance 75 (= "bodyWidth / 2") ExtraOffset 0
sketch "A Facet 315 Triangle 1" plane through (0, 53.033, -53.033) normal (0, 0.7071, -0.7071) x axis (1, 0, 0)
  line L1 (-62.2721, -27.066) -> (-23.9949, 27.066)
  line L2 (25.3367, 27.066) -> (-62.2721, -27.066)
  line L3 (-23.9949, 27.066) -> (25.3367, 27.066)
  line L4 (-47.6674, -13.34) -> (-21.9244, 23.066)
  line L5 (11.2532, 23.066) -> (-47.6674, -13.34)
  line L6 (-21.9244, 23.066) -> (11.2532, 23.066)
  point P1 (0, 0)
  point P2 (-23.9949, 27.066)
  point P3 (-62.2721, -27.066)
  point P4 (25.3367, 27.066)
  dimension "d294" distance P1 P2 = 23.9949 (= "Linear Dimension-2")
  dimension "d295" distance P1 P2 = 27.066 (= "Linear Dimension-3")
  dimension "d296" distance P1 P3 = 62.2721 (= "Linear Dimension-4")
  dimension "d297" distance P1 P3 = 27.066 (= "Linear Dimension-5")
  dimension "d298" distance P1 P4 = 25.3367 (= "Linear Dimension-6")
  dimension "d299" distance P1 P4 = 27.066 (= "Linear Dimension-7")
  dimension "d300" = -4 (= "-memberWidth / 2")
extrude "Extrude21" cut sketch "A Facet 315 Triangle 1" profile of L5 L6 L4 against normal blind 4.7 (magnitude of "-( wall + 0.2 mm )")
sketch "A Facet 315 Triangle 2" plane through (0, 53.033, -53.033) normal (0, 0.7071, -0.7071) x axis (1, 0, 0)
  line L1 (25.3367, 27.066) -> (-62.2721, -27.066)
  line L2 (61.9093, -27.066) -> (25.3367, 27.066)
  line L3 (-62.2721, -27.066) -> (61.9093, -27.066)
  line L4 (24.1722, 21.6445) -> (-48.1886, -23.066)
  line L5 (54.3795, -23.066) -> (24.1722, 21.6445)
  line L6 (-48.1886, -23.066) -> (54.3795, -23.066)
  point P1 (0, 0)
  point P2 (-62.2721, -27.066)
  point P3 (25.3367, 27.066)
  point P4 (61.9093, -27.066)
  dimension "d303" distance P1 P2 = 62.2721 (= "Linear Dimension-2")
  dimension "d304" distance P1 P2 = 27.066 (= "Linear Dimension-3")
  dimension "d305" distance P1 P3 = 25.3367 (= "Linear Dimension-4")
  dimension "d306" distance P1 P3 = 27.066 (= "Linear Dimension-5")
  dimension "d307" distance P1 P4 = 61.9093 (= "Linear Dimension-6")
  dimension "d308" distance P1 P4 = 27.066 (= "Linear Dimension-7")
  dimension "d309" = 4 (= "memberWidth / 2")
extrude "Extrude22" cut sketch "A Facet 315 Triangle 2" profile of L5 L6 L4 against normal blind 4.7 (magnitude of "-( wall + 0.2 mm )")
sketch "A Facet 315 Triangle 3" plane through (0, 53.033, -53.033) normal (0, 0.7071, -0.7071) x axis (1, 0, 0)
  line L1 (61.9093, -27.066) -> (25.3367, 27.066)
  line L2 (124, 27.066) -> (61.9093, -27.066)
  line L3 (25.3367, 27.066) -> (124, 27.066)
  line L4 (62.6909, -21.0779) -> (32.8665, 23.066)
  line L5 (113.325, 23.066) -> (62.6909, -21.0779)
  line L6 (32.8665, 23.066) -> (113.325, 23.066)
  point P1 (0, 0)
  point P2 (25.3367, 27.066)
  point P3 (61.9093, -27.066)
  point P4 (124, 27.066)
  dimension "d312" distance P1 P2 = 25.3367 (= "Linear Dimension-2")
  dimension "d313" distance P1 P2 = 27.066 (= "Linear Dimension-3")
  dimension "d314" distance P1 P3 = 61.9093 (= "Linear Dimension-4")
  dimension "d315" distance P1 P3 = 27.066 (= "Linear Dimension-5")
  dimension "d316" distance P1 P4 = 124 (= "Linear Dimension-6")
  dimension "d317" distance P1 P4 = 27.066 (= "Linear Dimension-7")
  dimension "d318" = -4 (= "-memberWidth / 2")
extrude "Extrude23" cut sketch "A Facet 315 Triangle 3" profile of L5 L6 L4 against normal blind 4.7 (magnitude of "-( wall + 0.2 mm )")
sketch "A Facet 315 Triangle 4" plane through (0, 53.033, -53.033) normal (0, 0.7071, -0.7071) x axis (1, 0, 0)
  line L1 (124, 27.066) -> (61.9093, -27.066)
  line L2 (124, -27.066) -> (124, 27.066)
  line L3 (61.9093, -27.066) -> (124, -27.066)
  line L4 (120, 18.272) -> (72.5843, -23.066)
  line L5 (120, -23.066) -> (120, 18.272)
  line L6 (72.5843, -23.066) -> (120, -23.066)
  point P1 (0, 0)
  point P2 (61.9093, -27.066)
  point P3 (124, 27.066)
  point P4 (124, -27.066)
  dimension "d321" distance P1 P2 = 61.9093 (= "Linear Dimension-2")
  dimension "d322" distance P1 P2 = 27.066 (= "Linear Dimension-3")
  dimension "d323" distance P1 P3 = 124 (= "Linear Dimension-4")
  dimension "d324" distance P1 P3 = 27.066 (= "Linear Dimension-5")
  dimension "d325" distance P1 P4 = 124 (= "Linear Dimension-6")
  dimension "d326" distance P1 P4 = 27.066 (= "Linear Dimension-7")
  dimension "d327" = 4 (= "memberWidth / 2")
extrude "Extrude24" cut sketch "A Facet 315 Triangle 4" profile of L5 L6 L4 against normal blind 4.7 (magnitude of "-( wall + 0.2 mm )")
fillet "Fillet8" radius 1.5 (= "apertureRadius")
work_plane "WorkPlane1" RotateAngle -90 ExtraOffset 0
work_plane "WorkPlane2" AlongDistance 75 (= "bodyWidth / 2") ExtraOffset 0
sketch "B Facet 0 Triangle 1" plane through (0, 75, 0) normal (0, 1, 0) x axis (1, 0, 0)
  line L1 (-84.8995, -27.066) -> (-84.8995, 27.066)
  line L2 (-124, 27.066) -> (-84.8995, -27.066)
  line L3 (-84.8995, 27.066) -> (-124, 27.066)
  line L4 (-88.8995, -14.697) -> (-88.8995, 23.066)
  line L5 (-116.1764, 23.066) -> (-88.8995, -14.697)
  line L6 (-88.8995, 23.066) -> (-116.1764, 23.066)
  point P1 (0, 0)
  point P2 (-84.8995, 27.066)
  point P3 (-84.8995, -27.066)
  point P4 (-124, 27.066)
  dimension "d336" distance P1 P2 = 84.8995 (= "Linear Dimension-2")
  dimension "d337" distance P1 P2 = 27.066 (= "Linear Dimension-3")
  dimension "d338" distance P1 P3 = 84.8995 (= "Linear Dimension-4")
  dimension "d339" distance P1 P3 = 27.066 (= "Linear Dimension-5")
  dimension "d340" distance P1 P4 = 124 (= "Linear Dimension-6")
  dimension "d341" distance P1 P4 = 27.066 (= "Linear Dimension-7")
  dimension "d342" = 4 (= "memberWidth / 2")
extrude "Extrude1" cut sketch "B Facet 0 Triangle 1" profile of L5 L6 L4 against normal blind 4.7 (magnitude of "-( wall + 0.2 mm )")
sketch "B Facet 0 Triangle 2" plane through (0, 75, 0) normal (0, 1, 0) x axis (1, 0, 0)
  line L1 (-124, 27.066) -> (-84.8995, -27.066)
  line L2 (-124, -27.066) -> (-124, 27.066)
  line L3 (-84.8995, -27.066) -> (-124, -27.066)
  line L4 (-120, 14.697) -> (-92.7231, -23.066)
  line L5 (-120, -23.066) -> (-120, 14.697)
  line L6 (-92.7231, -23.066) -> (-120, -23.066)
  point P1 (0, 0)
  point P2 (-84.8995, -27.066)
  point P3 (-124, 27.066)
  point P4 (-124, -27.066)
  dimension "d345" distance P1 P2 = 84.8995 (= "Linear Dimension-2")
  dimension "d346" distance P1 P2 = 27.066 (= "Linear Dimension-3")
  dimension "d347" distance P1 P3 = 124 (= "Linear Dimension-4")
  dimension "d348" distance P1 P3 = 27.066 (= "Linear Dimension-5")
  dimension "d349" distance P1 P4 = 124 (= "Linear Dimension-6")
  dimension "d350" distance P1 P4 = 27.066 (= "Linear Dimension-7")
  dimension "d351" = -4 (= "-memberWidth / 2")
extrude "Extrude2" cut sketch "B Facet 0 Triangle 2" profile of L5 L6 L4 against normal blind 4.7 (magnitude of "-( wall + 0.2 mm )")
fillet "Fillet1" radius 1.5 (= "apertureRadius")
work_plane "WorkPlane3" RotateAngle -45 ExtraOffset 0
work_plane "WorkPlane4" AlongDistance 75 (= "bodyWidth / 2") ExtraOffset 0
sketch "B Facet 45 Triangle 1" plane through (0, 53.033, 53.033) normal (0, 0.7071, 0.7071) x axis (1, 0, 0)
  line L1 (-43.7939, -27.066) -> (-82.0711, 27.066)
  line L2 (-124, 27.066) -> (-43.7939, -27.066)
  line L3 (-82.0711, 27.066) -> (-124, 27.066)
  line L4 (-59.6927, -11.51) -> (-84.1416, 23.066)
  line L5 (-110.9231, 23.066) -> (-59.6927, -11.51)
  line L6 (-84.1416, 23.066) -> (-110.9231, 23.066)
  point P1 (0, 0)
  point P2 (-82.0711, 27.066)
  point P3 (-43.7939, -27.066)
  point P4 (-124, 27.066)
  dimension "d360" distance P1 P2 = 82.0711 (= "Linear Dimension-2")
  dimension "d361" distance P1 P2 = 27.066 (= "Linear Dimension-3")
  dimension "d362" distance P1 P3 = 43.7939 (= "Linear Dimension-4")
  dimension "d363" distance P1 P3 = 27.066 (= "Linear Dimension-5")
  dimension "d364" distance P1 P4 = 124 (= "Linear Dimension-6")
  dimension "d365" distance P1 P4 = 27.066 (= "Linear Dimension-7")
  dimension "d366" = 4 (= "memberWidth / 2")
extrude "Extrude3" cut sketch "B Facet 45 Triangle 1" profile of L5 L6 L4 against normal blind 4.7 (magnitude of "-( wall + 0.2 mm )")
sketch "B Facet 45 Triangle 2" plane through (0, 53.033, 53.033) normal (0, 0.7071, 0.7071) x axis (1, 0, 0)
  line L1 (-124, 27.066) -> (-43.7939, -27.066)
  line L2 (-124, -27.066) -> (-124, 27.066)
  line L3 (-43.7939, -27.066) -> (-124, -27.066)
  line L4 (-120, 19.5406) -> (-56.8709, -23.066)
  line L5 (-120, -23.066) -> (-120, 19.5406)
  line L6 (-56.8709, -23.066) -> (-120, -23.066)
  point P1 (0, 0)
  point P2 (-43.7939, -27.066)
  point P3 (-124, 27.066)
  point P4 (-124, -27.066)
  dimension "d369" distance P1 P2 = 43.7939 (= "Linear Dimension-2")
  dimension "d370" distance P1 P2 = 27.066 (= "Linear Dimension-3")
  dimension "d371" distance P1 P3 = 124 (= "Linear Dimension-4")
  dimension "d372" distance P1 P3 = 27.066 (= "Linear Dimension-5")
  dimension "d373" distance P1 P4 = 124 (= "Linear Dimension-6")
  dimension "d374" distance P1 P4 = 27.066 (= "Linear Dimension-7")
  dimension "d375" = -4 (= "-memberWidth / 2")
extrude "Extrude4" cut sketch "B Facet 45 Triangle 2" profile of L5 L6 L4 against normal blind 4.7 (magnitude of "-( wall + 0.2 mm )")
fillet "Fillet2" radius 1.5 (= "apertureRadius")
work_plane "WorkPlane5" RotateAngle 0 ExtraOffset 0
work_plane "WorkPlane6" AlongDistance 75 (= "bodyWidth / 2") ExtraOffset 0
sketch "B Facet 90 Triangle 1" plane through (0, 0, 75) normal (0, 0, 1) x axis (1, 0, 0)
  line L1 (-36.9655, 27.066) -> (17.1665, -27.066)
  line L2 (-53.4167, -27.066) -> (-36.9655, 27.066)
  line L3 (17.1665, -27.066) -> (-53.4167, -27.066)
  line L4 (-35.0777, 19.5214) -> (7.5097, -23.066)
  line L5 (-48.0205, -23.066) -> (-35.0777, 19.5214)
  line L6 (7.5097, -23.066) -> (-48.0205, -23.066)
  point P1 (0, 0)
  point P2 (17.1665, -27.066)
  point P3 (-36.9655, 27.066)
  point P4 (-53.4167, -27.066)
  dimension "d384" distance P1 P2 = 17.1665 (= "Linear Dimension-2")
  dimension "d385" distance P1 P2 = 27.066 (= "Linear Dimension-3")
  dimension "d386" distance P1 P3 = 36.9655 (= "Linear Dimension-4")
  dimension "d387" distance P1 P3 = 27.066 (= "Linear Dimension-5")
  dimension "d388" distance P1 P4 = 53.4167 (= "Linear Dimension-6")
  dimension "d389" distance P1 P4 = 27.066 (= "Linear Dimension-7")
  dimension "d390" = -4 (= "-memberWidth / 2")
extrude "Extrude5" cut sketch "B Facet 90 Triangle 1" profile of L5 L6 L4 against normal blind 4.7 (magnitude of "-( wall + 0.2 mm )")
sketch "B Facet 90 Triangle 2" plane through (0, 0, 75) normal (0, 0, 1) x axis (1, 0, 0)
  line L1 (-53.4167, -27.066) -> (-36.9655, 27.066)
  line L2 (-124, 27.066) -> (-53.4167, -27.066)
  line L3 (-36.9655, 27.066) -> (-124, 27.066)
  line L4 (-55.5648, -20.3777) -> (-42.3618, 23.066)
  line L5 (-112.2115, 23.066) -> (-55.5648, -20.3777)
  line L6 (-42.3618, 23.066) -> (-112.2115, 23.066)
  point P1 (0, 0)
  point P2 (-36.9655, 27.066)
  point P3 (-53.4167, -27.066)
  point P4 (-124, 27.066)
  dimension "d393" distance P1 P2 = 36.9655 (= "Linear Dimension-2")
  dimension "d394" distance P1 P2 = 27.066 (= "Linear Dimension-3")
  dimension "d395" distance P1 P3 = 53.4167 (= "Linear Dimension-4")
  dimension "d396" distance P1 P3 = 27.066 (= "Linear Dimension-5")
  dimension "d397" distance P1 P4 = 124 (= "Linear Dimension-6")
  dimension "d398" distance P1 P4 = 27.066 (= "Linear Dimension-7")
  dimension "d399" = 4 (= "memberWidth / 2")
extrude "Extrude6" cut sketch "B Facet 90 Triangle 2" profile of L5 L6 L4 against normal blind 4.7 (magnitude of "-( wall + 0.2 mm )")
sketch "B Facet 90 Triangle 3" plane through (0, 0, 75) normal (0, 0, 1) x axis (1, 0, 0)
  line L1 (-124, 27.066) -> (-53.4167, -27.066)
  line L2 (-124, -27.066) -> (-124, 27.066)
  line L3 (-53.4167, -27.066) -> (-124, -27.066)
  line L4 (-120, 18.9574) -> (-65.2053, -23.066)
  line L5 (-120, -23.066) -> (-120, 18.9574)
  line L6 (-65.2053, -23.066) -> (-120, -23.066)
  point P1 (0, 0)
  point P2 (-53.4167, -27.066)
  point P3 (-124, 27.066)
  point P4 (-124, -27.066)
  dimension "d402" distance P1 P2 = 53.4167 (= "Linear Dimension-2")
  dimension "d403" distance P1 P2 = 27.066 (= "Linear Dimension-3")
  dimension "d404" distance P1 P3 = 124 (= "Linear Dimension-4")
  dimension "d405" distance P1 P3 = 27.066 (= "Linear Dimension-5")
  dimension "d406" distance P1 P4 = 124 (= "Linear Dimension-6")
  dimension "d407" distance P1 P4 = 27.066 (= "Linear Dimension-7")
  dimension "d408" = -4 (= "-memberWidth / 2")
extrude "Extrude7" cut sketch "B Facet 90 Triangle 3" profile of L5 L6 L4 against normal blind 4.7 (magnitude of "-( wall + 0.2 mm )")
fillet "Fillet3" radius 1.5 (= "apertureRadius")
work_plane "WorkPlane7" RotateAngle 45 ExtraOffset 0
work_plane "WorkPlane8" AlongDistance 75 (= "bodyWidth / 2") ExtraOffset 0
sketch "B Facet 135 Triangle 1" plane through (0, -53.033, 53.033) normal (0, -0.7071, 0.7071) x axis (1, 0, 0)
  line L1 (62.2721, -27.066) -> (23.9949, 27.066)
  line L2 (-25.3367, 27.066) -> (62.2721, -27.066)
  line L3 (23.9949, 27.066) -> (-25.3367, 27.066)
  line L4 (47.6674, -13.34) -> (21.9244, 23.066)
  line L5 (-11.2532, 23.066) -> (47.6674, -13.34)
  line L6 (21.9244, 23.066) -> (-11.2532, 23.066)
  point P1 (0, 0)
  point P2 (23.9949, 27.066)
  point P3 (62.2721, -27.066)
  point P4 (-25.3367, 27.066)
  dimension "d417" distance P1 P2 = 23.9949 (= "Linear Dimension-2")
  dimension "d418" distance P1 P2 = 27.066 (= "Linear Dimension-3")
  dimension "d419" distance P1 P3 = 62.2721 (= "Linear Dimension-4")
  dimension "d420" distance P1 P3 = 27.066 (= "Linear Dimension-5")
  dimension "d421" distance P1 P4 = 25.3367 (= "Linear Dimension-6")
  dimension "d422" distance P1 P4 = 27.066 (= "Linear Dimension-7")
  dimension "d423" = 4 (= "memberWidth / 2")
extrude "Extrude8" cut sketch "B Facet 135 Triangle 1" profile of L5 L6 L4 against normal blind 4.7 (magnitude of "-( wall + 0.2 mm )")
sketch "B Facet 135 Triangle 2" plane through (0, -53.033, 53.033) normal (0, -0.7071, 0.7071) x axis (1, 0, 0)
  line L1 (-25.3367, 27.066) -> (62.2721, -27.066)
  line L2 (-61.9093, -27.066) -> (-25.3367, 27.066)
  line L3 (62.2721, -27.066) -> (-61.9093, -27.066)
  line L4 (-24.1722, 21.6445) -> (48.1886, -23.066)
  line L5 (-54.3795, -23.066) -> (-24.1722, 21.6445)
  line L6 (48.1886, -23.066) -> (-54.3795, -23.066)
  point P1 (0, 0)
  point P2 (62.2721, -27.066)
  point P3 (-25.3367, 27.066)
  point P4 (-61.9093, -27.066)
  dimension "d426" distance P1 P2 = 62.2721 (= "Linear Dimension-2")
  dimension "d427" distance P1 P2 = 27.066 (= "Linear Dimension-3")
  dimension "d428" distance P1 P3 = 25.3367 (= "Linear Dimension-4")
  dimension "d429" distance P1 P3 = 27.066 (= "Linear Dimension-5")
  dimension "d430" distance P1 P4 = 61.9093 (= "Linear Dimension-6")
  dimension "d431" distance P1 P4 = 27.066 (= "Linear Dimension-7")
  dimension "d432" = -4 (= "-memberWidth / 2")
extrude "Extrude9" cut sketch "B Facet 135 Triangle 2" profile of L5 L6 L4 against normal blind 4.7 (magnitude of "-( wall + 0.2 mm )")
sketch "B Facet 135 Triangle 3" plane through (0, -53.033, 53.033) normal (0, -0.7071, 0.7071) x axis (1, 0, 0)
  line L1 (-61.9093, -27.066) -> (-25.3367, 27.066)
  line L2 (-124, 27.066) -> (-61.9093, -27.066)
  line L3 (-25.3367, 27.066) -> (-124, 27.066)
  line L4 (-62.6909, -21.0779) -> (-32.8665, 23.066)
  line L5 (-113.325, 23.066) -> (-62.6909, -21.0779)
  line L6 (-32.8665, 23.066) -> (-113.325, 23.066)
  point P1 (0, 0)
  point P2 (-25.3367, 27.066)
  point P3 (-61.9093, -27.066)
  point P4 (-124, 27.066)
  dimension "d435" distance P1 P2 = 25.3367 (= "Linear Dimension-2")
  dimension "d436" distance P1 P2 = 27.066 (= "Linear Dimension-3")
  dimension "d437" distance P1 P3 = 61.9093 (= "Linear Dimension-4")
  dimension "d438" distance P1 P3 = 27.066 (= "Linear Dimension-5")
  dimension "d439" distance P1 P4 = 124 (= "Linear Dimension-6")
  dimension "d440" distance P1 P4 = 27.066 (= "Linear Dimension-7")
  dimension "d441" = 4 (= "memberWidth / 2")
extrude "Extrude10" cut sketch "B Facet 135 Triangle 3" profile of L5 L6 L4 against normal blind 4.7 (magnitude of "-( wall + 0.2 mm )")
sketch "B Facet 135 Triangle 4" plane through (0, -53.033, 53.033) normal (0, -0.7071, 0.7071) x axis (1, 0, 0)
  line L1 (-124, 27.066) -> (-61.9093, -27.066)
  line L2 (-124, -27.066) -> (-124, 27.066)
  line L3 (-61.9093, -27.066) -> (-124, -27.066)
  line L4 (-120, 18.272) -> (-72.5843, -23.066)
  line L5 (-120, -23.066) -> (-120, 18.272)
  line L6 (-72.5843, -23.066) -> (-120, -23.066)
  point P1 (0, 0)
  point P2 (-61.9093, -27.066)
  point P3 (-124, 27.066)
  point P4 (-124, -27.066)
  dimension "d444" distance P1 P2 = 61.9093 (= "Linear Dimension-2")
  dimension "d445" distance P1 P2 = 27.066 (= "Linear Dimension-3")
  dimension "d446" distance P1 P3 = 124 (= "Linear Dimension-4")
  dimension "d447" distance P1 P3 = 27.066 (= "Linear Dimension-5")
  dimension "d448" distance P1 P4 = 124 (= "Linear Dimension-6")
  dimension "d449" distance P1 P4 = 27.066 (= "Linear Dimension-7")
  dimension "d450" = -4 (= "-memberWidth / 2")
extrude "Extrude11" cut sketch "B Facet 135 Triangle 4" profile of L5 L6 L4 against normal blind 4.7 (magnitude of "-( wall + 0.2 mm )")
fillet "Fillet4" radius 1.5 (= "apertureRadius")
work_plane "WorkPlane9" RotateAngle 90 ExtraOffset 0
work_plane "WorkPlane10" AlongDistance 75 (= "bodyWidth / 2") ExtraOffset 0
sketch "B Facet 180 Triangle 1" plane through (0, -75, 0) normal (0, -1, 0) x axis (-1, 0, 0)
  line L1 (-65.1005, 27.066) -> (-65.1005, -27.066)
  line L2 (-2.067, -27.066) -> (-65.1005, 27.066)
  line L3 (-65.1005, -27.066) -> (-2.067, -27.066)
  line L4 (-61.1005, 18.3583) -> (-61.1005, -23.066)
  line L5 (-12.8644, -23.066) -> (-61.1005, 18.3583)
  line L6 (-61.1005, -23.066) -> (-12.8644, -23.066)
  point P1 (0, 0)
  point P2 (-65.1005, -27.066)
  point P3 (-65.1005, 27.066)
  point P4 (-2.067, -27.066)
  dimension "d459" distance P1 P2 = 65.1005 (= "Linear Dimension-2")
  dimension "d460" distance P1 P2 = 27.066 (= "Linear Dimension-3")
  dimension "d461" distance P1 P3 = 65.1005 (= "Linear Dimension-4")
  dimension "d462" distance P1 P3 = 27.066 (= "Linear Dimension-5")
  dimension "d463" distance P1 P4 = 2.067 (= "Linear Dimension-6")
  dimension "d464" distance P1 P4 = 27.066 (= "Linear Dimension-7")
  dimension "d465" = 4 (= "memberWidth / 2")
extrude "Extrude12" cut sketch "B Facet 180 Triangle 1" profile of L5 L6 L4 against normal blind 4.7 (magnitude of "-( wall + 0.2 mm )")
sketch "B Facet 180 Triangle 2" plane through (0, -75, 0) normal (0, -1, 0) x axis (-1, 0, 0)
  line L1 (-2.067, -27.066) -> (-65.1005, 27.066)
  line L2 (60.9665, 27.066) -> (-2.067, -27.066)
  line L3 (-65.1005, 27.066) -> (60.9665, 27.066)
  line L4 (-2.067, -21.7934) -> (-54.3031, 23.066)
  line L5 (50.1691, 23.066) -> (-2.067, -21.7934)
  line L6 (-54.3031, 23.066) -> (50.1691, 23.066)
  point P1 (0, 0)
  point P2 (-65.1005, 27.066)
  point P3 (-2.067, -27.066)
  point P4 (60.9665, 27.066)
  dimension "d468" distance P1 P2 = 65.1005 (= "Linear Dimension-2")
  dimension "d469" distance P1 P2 = 27.066 (= "Linear Dimension-3")
  dimension "d470" distance P1 P3 = 2.067 (= "Linear Dimension-4")
  dimension "d471" distance P1 P3 = 27.066 (= "Linear Dimension-5")
  dimension "d472" distance P1 P4 = 60.9665 (= "Linear Dimension-6")
  dimension "d473" distance P1 P4 = 27.066 (= "Linear Dimension-7")
  dimension "d474" = -4 (= "-memberWidth / 2")
extrude "Extrude13" cut sketch "B Facet 180 Triangle 2" profile of L5 L6 L4 against normal blind 4.7 (magnitude of "-( wall + 0.2 mm )")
